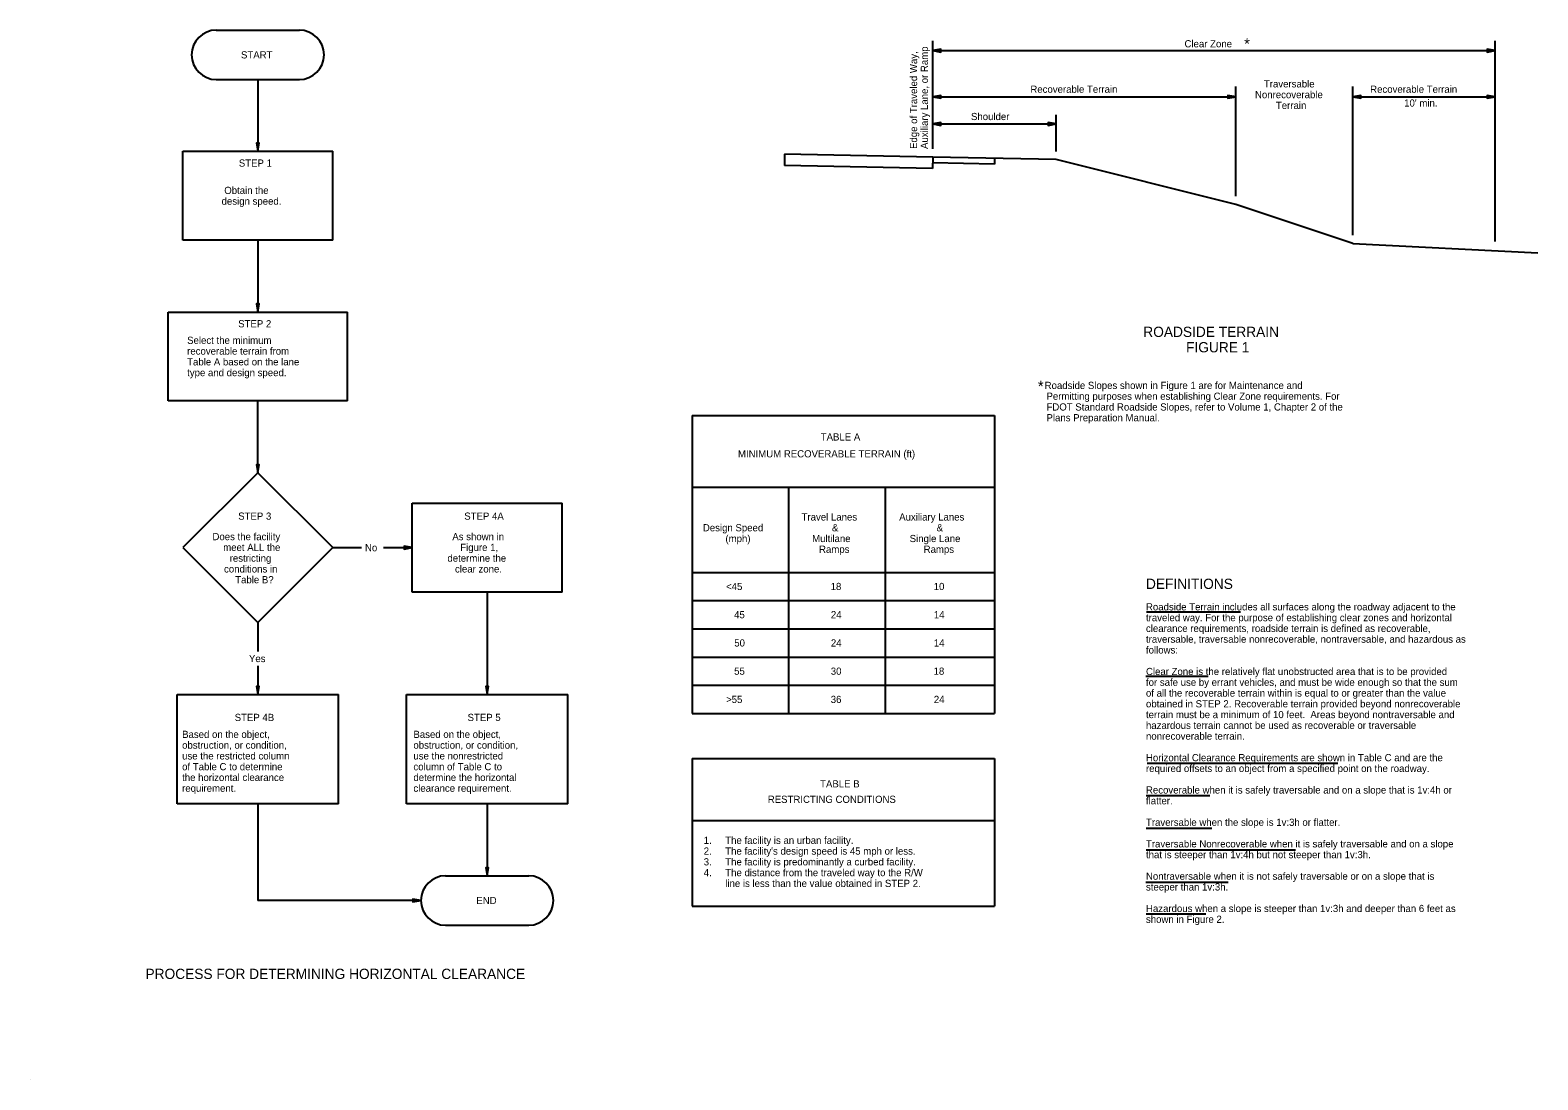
# Model space of a CAD drawing. Extents: x 10000 to 10735, y 10000 to 10512.
import ezdxf

# ---------------------------------------------------------------- set-up
doc = ezdxf.new("R2010")
doc.units = 0
for name, color, linetype in [('AdhocPoint_dp', 7, 'Continuous'), ('Default', 7, 'Continuous'), ('Dimension', 7, 'Continuous'), ('IndexDetail_1', 7, 'Continuous'), ('TextStructures', 7, 'Continuous')]:
    doc.layers.add(name, color=color, linetype=linetype)

msp = doc.modelspace()

# ---------------------------------------------------------------- linework, layer by layer
at = {"layer": 'AdhocPoint_dp'}
msp.add_line((10000, 10000), (10000, 10000), dxfattribs=at)
msp.add_line((10000, 10000), (10000, 10000), dxfattribs=at)
msp.add_line((10000, 10000), (10000, 10000), dxfattribs=at)
at = {"layer": 'Default'}
msp.add_line((10000, 10000), (10000, 10000), dxfattribs=at)
msp.add_line((10000, 10000), (10000, 10000), dxfattribs=at)
msp.add_line((10000, 10000), (10000, 10000), dxfattribs=at)
at = {"layer": 'Dimension'}
for p, q in [((10439.8, 10453.67), (10439.8, 10506.39)), ((10713.85, 10408.62), (10713.85, 10506.39)), ((10439.8, 10501.57), (10713.85, 10501.57)), ((10110.93, 10487.51), (10110.93, 10452.51)), ((10587.46, 10430.59), (10587.46, 10484.03)), ((10644.52, 10411.57), (10644.52, 10484.03)), ((10439.8, 10479.02), (10587.46, 10479.02)), ((10644.52, 10479.02), (10713.85, 10479.02)), ((10499.94, 10452.47), (10499.94, 10470.23)), ((10439.8, 10465.83), (10499.94, 10465.83)), ((10110.93, 10409.2), (10110.93, 10374.2)), ((10110.93, 10295.89), (10110.93, 10330.89)), ((10147.46, 10259.36), (10161.41, 10259.36)), ((10172.21, 10259.36), (10186.16, 10259.36)), ((10222.69, 10237.7), (10222.69, 10187.83)), ((10110.93, 10222.83), (10110.93, 10208.83)), ((10110.93, 10201.83), (10110.93, 10187.83)), ((10110.93, 10134.44), (10110.93, 10087.41)), ((10222.69, 10134.44), (10222.69, 10099.44)), ((10190.42, 10087.41), (10110.93, 10087.41))]:
    msp.add_line(p, q, dxfattribs=at)
for points in [[(10439.8, 10501.57), (10443.71, 10500.91), (10443.71, 10502.24)], [(10713.85, 10501.57), (10709.94, 10502.24), (10709.94, 10500.91)], [(10439.8, 10479.02), (10443.71, 10478.36), (10443.71, 10479.68)], [(10587.46, 10479.02), (10583.55, 10479.68), (10583.55, 10478.36)], [(10644.52, 10479.02), (10648.43, 10478.36), (10648.43, 10479.68)], [(10713.85, 10479.02), (10709.94, 10479.68), (10709.94, 10478.36)], [(10439.8, 10465.83), (10443.71, 10465.17), (10443.71, 10466.49)], [(10499.94, 10465.83), (10496.03, 10466.49), (10496.03, 10465.17)], [(10110.93, 10452.51), (10111.59, 10456.41), (10110.27, 10456.41)], [(10110.93, 10374.2), (10111.59, 10378.11), (10110.27, 10378.11)], [(10110.93, 10295.89), (10111.59, 10299.8), (10110.27, 10299.8)], [(10186.16, 10259.36), (10182.25, 10260.03), (10182.25, 10258.7)], [(10110.93, 10187.83), (10111.59, 10191.74), (10110.27, 10191.74)], [(10222.69, 10187.83), (10223.35, 10191.74), (10222.02, 10191.74)], [(10222.69, 10099.44), (10223.35, 10103.35), (10222.02, 10103.35)], [(10190.42, 10087.41), (10186.51, 10088.08), (10186.51, 10086.75)]]:
    msp.add_lwpolyline(points, close=True, dxfattribs=at)
at = {"layer": 'IndexDetail_1'}
for p, q in [((10090.69, 10511.56), (10131.17, 10511.56)), ((10090.69, 10487.51), (10131.17, 10487.51)), ((10074.4, 10430.85), (10074.4, 10452.51)), ((10074.4, 10452.51), (10147.46, 10452.51)), ((10147.46, 10430.85), (10147.46, 10452.51)), ((10367.64, 10451.11), (10367.53, 10445.59)), ((10439.8, 10449.66), (10367.64, 10451.11)), ((10439.8, 10449.66), (10439.69, 10444.15)), ((10469.81, 10446.31), (10439.75, 10446.91)), ((10499.94, 10448.46), (10439.8, 10449.66)), ((10469.87, 10449.06), (10469.81, 10446.31)), ((10587.46, 10426.58), (10499.94, 10448.46)), ((10439.69, 10444.15), (10367.53, 10445.59)), ((10074.4, 10409.2), (10074.4, 10430.85)), ((10147.46, 10409.2), (10147.46, 10430.85)), ((10644.52, 10407.56), (10587.46, 10426.58)), ((10147.46, 10409.2), (10074.4, 10409.2)), ((10644.52, 10407.56), (10734.63, 10403.05)), ((10067.21, 10374.2), (10154.66, 10374.2)), ((10067.21, 10352.54), (10067.21, 10374.2)), ((10154.66, 10352.54), (10154.66, 10374.2)), ((10067.21, 10330.89), (10067.21, 10352.54)), ((10154.66, 10330.89), (10154.66, 10352.54)), ((10154.66, 10330.89), (10067.21, 10330.89)), ((10322.52, 10323.73), (10322.52, 10178.53)), ((10322.52, 10323.73), (10469.84, 10323.73)), ((10469.84, 10323.73), (10469.84, 10178.53)), ((10110.93, 10295.89), (10074.4, 10259.36)), ((10110.93, 10295.89), (10147.46, 10259.36)), ((10322.52, 10288.9), (10469.84, 10288.9)), ((10369.57, 10288.9), (10369.57, 10178.53)), ((10416.62, 10288.9), (10416.62, 10178.53)), ((10186.16, 10281.01), (10259.21, 10281.01)), ((10186.16, 10259.36), (10186.16, 10281.01)), ((10259.21, 10259.36), (10259.21, 10281.01)), ((10074.4, 10259.36), (10110.93, 10222.83)), ((10147.46, 10259.36), (10110.93, 10222.83)), ((10186.16, 10237.71), (10186.16, 10259.36)), ((10259.21, 10237.71), (10259.21, 10259.36)), ((10322.52, 10247.33), (10469.84, 10247.33)), ((10259.21, 10237.71), (10186.16, 10237.71)), ((10322.52, 10233.57), (10469.84, 10233.57)), ((10543.96, 10228.05), (10589.72, 10228.05)), ((10322.52, 10219.81), (10469.84, 10219.81)), ((10322.52, 10206.05), (10469.84, 10206.05)), ((10543.6, 10196.81), (10573.92, 10196.81)), ((10322.52, 10192.29), (10469.84, 10192.29)), ((10071.62, 10187.83), (10150.24, 10187.83)), ((10071.62, 10166.18), (10071.62, 10187.83)), ((10150.24, 10166.18), (10150.24, 10187.83)), ((10183.38, 10187.83), (10261.99, 10187.83)), ((10183.38, 10166.18), (10183.38, 10187.83)), ((10261.99, 10166.18), (10261.99, 10187.83)), ((10322.52, 10178.53), (10469.84, 10178.53)), ((10071.62, 10134.44), (10071.62, 10166.18)), ((10150.24, 10134.44), (10150.24, 10166.18)), ((10183.38, 10134.44), (10183.38, 10166.18)), ((10261.99, 10134.44), (10261.99, 10166.18)), ((10322.52, 10156.61), (10469.84, 10156.61)), ((10322.52, 10156.61), (10322.52, 10084.57)), ((10469.84, 10156.61), (10469.84, 10084.57)), ((10544.32, 10154.3), (10637.11, 10154.3)), ((10543.78, 10138.5), (10574.77, 10138.5)), ((10150.24, 10134.44), (10071.62, 10134.44)), ((10261.99, 10134.44), (10183.38, 10134.44)), ((10322.52, 10126.45), (10469.84, 10126.45)), ((10543.78, 10122.7), (10575.73, 10122.7)), ((10543.78, 10112.16), (10616.61, 10112.16)), ((10202.44, 10099.44), (10242.93, 10099.44)), ((10543.6, 10096.36), (10583.72, 10096.36)), ((10322.52, 10084.57), (10469.84, 10084.57)), ((10543.78, 10080.91), (10572.83, 10080.91)), ((10202.44, 10075.39), (10242.93, 10075.39))]:
    msp.add_line(p, q, dxfattribs=at)
for centre, start, end in [((10090.69, 10499.53), 90, 270), ((10131.17, 10499.53), 270, 90), ((10202.44, 10087.41), 90, 270), ((10242.93, 10087.41), 270, 90)]:
    msp.add_arc(centre, 12.03, start, end, dxfattribs=at)

# ---------------------------------------------------------------- texts
at = {"layer": 'TextStructures'}
for s, height, p in [('Clear Zone', 3.5, (10562.46, 10503.17)), ('*', 5.33, (10591.54, 10502.23)), ('START', 3.5, (10102.73, 10497.78)), ('Recoverable Terrain', 3.5, (10487.37, 10481.02)), ('Traversable', 3.5, (10601.15, 10483.64)), ('Recoverable Terrain', 3.5, (10652.92, 10481.02)), ('Nonrecoverable', 3.5, (10596.81, 10478.39)), ('Terrain', 3.5, (10607, 10473.14)), ("10' min.", 3.5, (10669.5, 10474.31)), ('Shoulder', 3.5, (10458.43, 10467.73)), ('STEP 1', 3.5, (10101.69, 10445.04)), (' Obtain the ', 3.5, (10093.28, 10431.73)), ('design speed.', 3.5, (10093.28, 10426.48)), ('STEP 2', 3.5, (10101.37, 10366.73)), ('ROADSIDE TERRAIN', 5, (10542.38, 10362.04)), ('Select the minimum', 3.5, (10076.5, 10358.67)), ('FIGURE 1', 5, (10563.23, 10354.54)), ('Table A based on the lane', 3.5, (10076.5, 10348.17)), ('recoverable terrain from ', 3.5, (10076.5, 10353.42)), ('type and design speed.', 3.5, (10076.5, 10342.92)), ('*', 5.33, (10491.03, 10335.34)), ('  Roadside Slopes shown in Figure 1 are for Maintenance and ', 3.5, (10491.72, 10336.68)), ('Permitting purposes when establishing Clear Zone requirements. For ', 3.5, (10495.22, 10331.43)), ('FDOT Standard Roadside Slopes, refer to Volume 1, Chapter 2 of the ', 3.5, (10495.22, 10326.18)), ('Plans Preparation Manual. ', 3.5, (10495.22, 10320.93)), ('TABLE A', 3.5, (10385.23, 10311.57)), ('MINIMUM RECOVERABLE TERRAIN (ft)', 3.5, (10344.88, 10303.35)), ('STEP 3', 3.5, (10101.37, 10272.98)), ('STEP 4A', 3.5, (10211.52, 10272.98)), ('Design Speed', 3.5, (10327.79, 10267.32)), ('Travel Lanes', 3.5, (10375.89, 10272.57)), ('&', 3.5, (10390.69, 10267.32)), ('Auxiliary Lanes', 3.5, (10423.44, 10272.57)), ('&', 3.5, (10441.67, 10267.32)), ('Does the facility', 3.5, (10088.83, 10263)), ('As shown in ', 3.5, (10205.7, 10263)), ('(mph)', 3.5, (10338.78, 10262.07)), ('Multilane', 3.5, (10381.03, 10262.07)), ('Single Lane', 3.5, (10428.55, 10262.07)), ('meet ALL the ', 3.5, (10094.07, 10257.75)), ('restricting', 3.5, (10097.23, 10252.5)), ('No', 3.5, (10163.15, 10257.61)), ('determine the ', 3.5, (10203.32, 10252.5)), ('Figure 1,', 3.5, (10209.55, 10257.75)), ('Ramps', 3.5, (10384.39, 10256.82)), ('Ramps', 3.5, (10435.36, 10256.82)), ('conditions in ', 3.5, (10094.47, 10247.25)), ('clear zone.', 3.5, (10207.01, 10247.25)), ('Table B?', 3.5, (10099.91, 10242)), ('<45', 3.5, (10339.09, 10238.7)), ('18', 3.5, (10390.04, 10238.7)), ('10', 3.5, (10440.27, 10238.7)), ('DEFINITIONS', 5, (10543.69, 10239.24)), ('45', 3.5, (10343.02, 10224.94)), ('24', 3.5, (10390.16, 10224.94)), ('14', 3.5, (10440.32, 10224.94)), ('traveled way. For the purpose of establishing clear zones and horizontal ', 3.5, (10543.69, 10223.52)), ('Roadside Terrain includes all surfaces along the roadway adjacent to the ', 3.5, (10543.69, 10228.77)), ('clearance requirements, roadside terrain is defined as recoverable, ', 3.5, (10543.69, 10218.27)), ('50', 3.5, (10343.08, 10211.18)), ('24', 3.5, (10390.16, 10211.18)), ('14', 3.5, (10440.32, 10211.18)), ('traversable, traversable nonrecoverable, nontraversable, and hazardous as ', 3.5, (10543.69, 10213.02)), ('follows:', 3.5, (10543.69, 10207.77)), ('Yes', 3.5, (10106.61, 10203.58)), ('55', 3.5, (10343.02, 10197.42)), ('30', 3.5, (10390.11, 10197.42)), ('18', 3.5, (10440.2, 10197.42)), ('Clear Zone is the relatively flat unobstructed area that is to be provided ', 3.5, (10543.69, 10197.27)), ('for safe use by errant vehicles, and must be wide enough so that the sum ', 3.5, (10543.69, 10192.02)), ('of all the recoverable terrain within is equal to or greater than the value ', 3.5, (10543.69, 10186.77)), ('>55', 3.5, (10339.09, 10183.66)), ('36', 3.5, (10390.09, 10183.66)), ('24', 3.5, (10440.32, 10183.66)), ('obtained in STEP 2. Recoverable terrain provided beyond nonrecoverable ', 3.5, (10543.69, 10181.52)), ('STEP 4B', 3.5, (10099.65, 10174.88)), ('STEP 5', 3.5, (10213.14, 10174.88)), ('terrain must be a minimum of 10 feet.  Areas beyond nontraversable and ', 3.5, (10543.69, 10176.27)), ('hazardous terrain cannot be used as recoverable or traversable ', 3.5, (10543.69, 10171.02)), ('Based on the object, ', 3.5, (10074.05, 10166.63)), ('Based on the object, ', 3.5, (10186.75, 10166.63)), ('nonrecoverable terrain.', 3.5, (10543.69, 10165.77)), ('obstruction, or condition, ', 3.5, (10074.05, 10161.38)), ('obstruction, or condition, ', 3.5, (10186.75, 10161.38)), ('of Table C to determine ', 3.5, (10074.05, 10150.88)), ('use the restricted column ', 3.5, (10074.05, 10156.13)), ('column of Table C to ', 3.5, (10186.75, 10150.88)), ('use the nonrestricted ', 3.5, (10186.75, 10156.13)), ('required offsets to an object from a specified point on the roadway.', 3.5, (10543.69, 10150.02)), ('Horizontal Clearance Requirements are shown in Table C and are the ', 3.5, (10543.69, 10155.27)), ('the horizontal clearance ', 3.5, (10074.05, 10145.63)), ('determine the horizontal ', 3.5, (10186.75, 10145.63)), ('TABLE B', 3.5, (10384.91, 10142.5)), ('requirement.', 3.5, (10074.05, 10140.38)), ('clearance requirement.', 3.5, (10186.75, 10140.38)), ('RESTRICTING CONDITIONS', 3.5, (10359.41, 10134.97)), ('flatter.', 3.5, (10543.69, 10134.27)), ('Recoverable when it is safely traversable and on a slope that is 1v:4h or ', 3.5, (10543.69, 10139.52)), ('Traversable when the slope is 1v:3h or flatter.', 3.5, (10543.69, 10123.77)), ('1.', 3.5, (10328.2, 10115)), ('The facility is an urban facility.', 3.5, (10338.7, 10115)), ('Traversable Nonrecoverable when it is safely traversable and on a slope ', 3.5, (10543.69, 10113.27)), ('2.', 3.5, (10328.2, 10109.75)), ("The facility's design speed is 45 mph or less.", 3.5, (10338.7, 10109.75)), ('that is steeper than 1v:4h but not steeper than 1v:3h.', 3.5, (10543.69, 10108.02)), ('4.', 3.5, (10328.2, 10099.25)), ('3.', 3.5, (10328.2, 10104.5)), ('The facility is predominantly a curbed facility.', 3.5, (10338.7, 10104.5)), ('The distance from the traveled way to the R/W', 3.5, (10338.7, 10099.25)), ('Nontraversable when it is not safely traversable or on a slope that is ', 3.5, (10543.69, 10097.52)), ('line is less than the value obtained in STEP 2.', 3.5, (10338.7, 10094)), ('steeper than 1v:3h.', 3.5, (10543.69, 10092.27)), ('END', 3.5, (10217.4, 10085.66)), ('shown in Figure 2.', 3.5, (10543.69, 10076.52)), ('Hazardous when a slope is steeper than 1v:3h and deeper than 6 feet as ', 3.5, (10543.69, 10081.77)), ('PROCESS FOR DETERMINING HORIZONTAL CLEARANCE ', 5, (10056.2, 10049.16))]:
    msp.add_text(s, height=height, dxfattribs=at).set_placement(p)
for s, p in [('Edge of Traveled Way, ', (10432.19, 10453.67)), ('Auxiliary Lane, or Ramp', (10437.44, 10453.67))]:
    msp.add_text(s, height=3.5, rotation=90, dxfattribs=at).set_placement(p)

doc.saveas('drawing.dxf')
